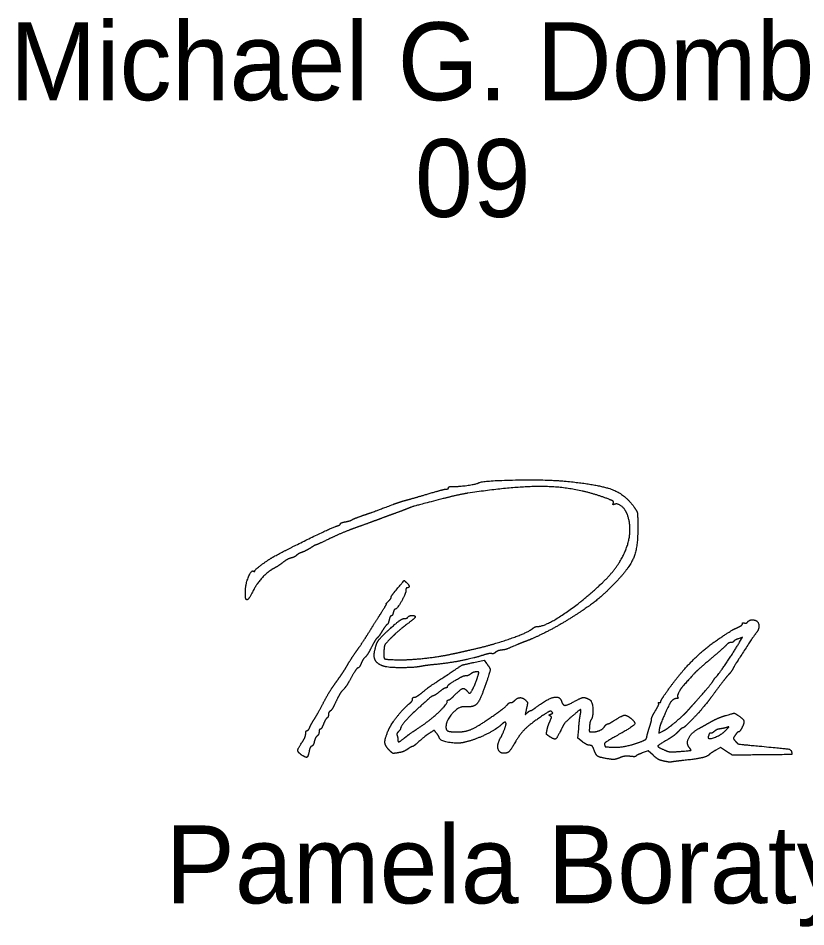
# Model space of a CAD drawing. Extents: x 0 to 40.8, y 0 to 22.
# Drawn here: x 37.682 to 39.097, y 9.315 to 10.949 of the extents above; entities that cross this region are included whole.
import ezdxf

# ---------------------------------------------------------------- set-up
doc = ezdxf.new("R2010")
doc.units = 0
doc.layers.add('Default', color=7, linetype='Continuous')
doc.layers.add('SH_Text', color=7, linetype='Continuous')

msp = doc.modelspace()

# ---------------------------------------------------------------- linework, layer by layer
at = {"layer": 'Default'}
for points in [[(38.9782, 9.8265), (38.9836, 9.8355), (38.9763, 9.8329)], [(38.5009, 9.7904), (38.5189, 9.7944), (38.5236, 9.7882)], [(38.6958, 9.6475), (38.6875, 9.6539), (38.689, 9.6709)], [(38.8338, 9.6695), (38.8328, 9.6631), (38.8415, 9.6675)], [(38.8228, 9.6232), (38.8136, 9.6315), (38.8031, 9.6274)], [(38.9547, 9.6302), (38.944, 9.637), (38.9356, 9.6325)]]:
    msp.add_lwpolyline(points, dxfattribs=at)
for points in [[(38.5083, 10.1129), (38.5151, 10.1171), (38.6321, 10.1194), (38.6665, 10.116)], [(38.6665, 10.116), (38.7258, 10.1102), (38.7733, 10.0919), (38.7891, 10.0689)], [(38.4186, 10.0933), (38.4346, 10.0981), (38.4495, 10.102), (38.4516, 10.102)], [(38.4516, 10.102), (38.4536, 10.102), (38.4553, 10.1031), (38.4553, 10.1045)], [(38.4553, 10.1045), (38.4553, 10.1059), (38.4594, 10.1069), (38.4643, 10.1067)], [(38.4643, 10.1067), (38.4739, 10.1064), (38.5049, 10.1108), (38.5083, 10.1129)], [(38.739, 10.0853), (38.6884, 10.1043), (38.5805, 10.1083), (38.4901, 10.0945)], [(38.3557, 10.0744), (38.3636, 10.0773), (38.3744, 10.0808), (38.3797, 10.0822)], [(38.3797, 10.0822), (38.385, 10.0836), (38.4025, 10.0886), (38.4186, 10.0933)], [(38.4457, 10.0848), (38.3947, 10.0716), (38.3904, 10.0704), (38.3797, 10.066)], [(38.4901, 10.0945), (38.4809, 10.0931), (38.4609, 10.0887), (38.4457, 10.0848)], [(38.7513, 10.0766), (38.7523, 10.0792), (38.7488, 10.0816), (38.739, 10.0853)], [(38.2993, 10.0538), (38.314, 10.0589), (38.3205, 10.0612), (38.3557, 10.0744)], [(38.3797, 10.066), (38.3771, 10.0649), (38.3668, 10.0611), (38.3569, 10.0575)], [(38.7537, 10.0746), (38.7511, 10.0736), (38.7504, 10.0742), (38.7513, 10.0766)], [(38.7771, 10.0547), (38.7739, 10.0644), (38.7594, 10.0768), (38.7537, 10.0746)], [(38.7891, 10.0689), (38.794, 10.0616), (38.795, 10.0573), (38.7953, 10.0394)], [(38.2813, 10.0466), (38.2826, 10.0476), (38.2907, 10.0508), (38.2993, 10.0538)], [(38.3569, 10.0575), (38.347, 10.0539), (38.3319, 10.0483), (38.3233, 10.0451)], [(38.7316, 9.9335), (38.7625, 9.9629), (38.7864, 10.0264), (38.7771, 10.0547)], [(38.1433, 9.9816), (38.1735, 9.9978), (38.2471, 10.0335), (38.2555, 10.0359)], [(38.2873, 10.032), (38.2761, 10.028), (38.2557, 10.0194), (38.2421, 10.013)], [(38.2555, 10.0359), (38.2585, 10.0368), (38.2609, 10.0384), (38.2609, 10.0395)], [(38.2609, 10.0395), (38.2609, 10.0406), (38.265, 10.0422), (38.2699, 10.0431)], [(38.2699, 10.0431), (38.2749, 10.0441), (38.28, 10.0456), (38.2813, 10.0466)], [(38.3233, 10.0451), (38.3147, 10.0419), (38.2985, 10.036), (38.2873, 10.032)], [(38.7953, 10.0394), (38.796, 9.9986), (38.7799, 9.9589), (38.7505, 9.929)], [(38.2162, 10.0012), (38.2157, 10.0012), (38.2112, 9.9987), (38.2063, 9.9955)], [(38.2421, 10.013), (38.2284, 10.0065), (38.2168, 10.0012), (38.2162, 10.0012)], [(38.1822, 9.9829), (38.1804, 9.9811), (38.1761, 9.9789), (38.1725, 9.978)], [(38.1914, 9.988), (38.1882, 9.987), (38.1841, 9.9847), (38.1822, 9.9829)], [(38.2063, 9.9955), (38.2013, 9.9924), (38.1947, 9.9891), (38.1914, 9.988)], [(38.1073, 9.955), (38.1073, 9.9571), (38.1327, 9.9759), (38.1433, 9.9816)], [(38.1577, 9.97), (38.1531, 9.9664), (38.1459, 9.9617), (38.1418, 9.9596)], [(38.1725, 9.978), (38.169, 9.9772), (38.1623, 9.9736), (38.1577, 9.97)], [(38.0901, 9.9171), (38.0902, 9.9303), (38.1009, 9.9569), (38.105, 9.9543)], [(38.105, 9.9543), (38.1063, 9.9536), (38.1073, 9.9538), (38.1073, 9.955)], [(38.1418, 9.9596), (38.1314, 9.9543), (38.1115, 9.9334), (38.1053, 9.9213)], [(38.3575, 9.916), (38.376, 9.9382), (38.3753, 9.9376), (38.3794, 9.9342)], [(38.3794, 9.9342), (38.3837, 9.9307), (38.3847, 9.9244), (38.3809, 9.9244)], [(38.1053, 9.9213), (38.0987, 9.9084), (38.0934, 9.9015), (38.0915, 9.9034)], [(38.3785, 9.9193), (38.3785, 9.9138), (38.3626, 9.886), (38.3594, 9.886)], [(38.3809, 9.9244), (38.3796, 9.9244), (38.3785, 9.9221), (38.3785, 9.9193)], [(38.6149, 9.8548), (38.629, 9.8548), (38.6971, 9.9007), (38.7316, 9.9335)], [(38.7505, 9.929), (38.7319, 9.9101), (38.6995, 9.8852), (38.669, 9.8664)], [(38.0915, 9.9034), (38.0907, 9.9042), (38.0901, 9.9104), (38.0901, 9.9171)], [(38.3473, 9.9004), (38.3499, 9.903), (38.3521, 9.9062), (38.3521, 9.9074)], [(38.3521, 9.9074), (38.3521, 9.9086), (38.3545, 9.9125), (38.3575, 9.916)], [(38.3346, 9.8799), (38.3401, 9.8885), (38.3441, 9.8956), (38.3436, 9.8956)], [(38.3436, 9.8956), (38.343, 9.8956), (38.3447, 9.8978), (38.3473, 9.9004)], [(38.3594, 9.886), (38.3583, 9.886), (38.3567, 9.8833), (38.3559, 9.88)], [(38.3125, 9.8449), (38.3191, 9.8556), (38.329, 9.8713), (38.3346, 9.8799)], [(38.3437, 9.845), (38.3594, 9.8597), (38.3722, 9.8692), (38.3761, 9.8692)], [(38.3522, 9.874), (38.3511, 9.874), (38.3494, 9.8708), (38.3485, 9.8668)], [(38.3559, 9.88), (38.3551, 9.8767), (38.3534, 9.874), (38.3522, 9.874)], [(38.3761, 9.8692), (38.3786, 9.8692), (38.3813, 9.8703), (38.3821, 9.8716)], [(38.3953, 9.872), (38.3953, 9.8709), (38.3886, 9.8649), (38.3803, 9.8588)], [(38.3821, 9.8716), (38.3839, 9.8745), (38.3953, 9.8748), (38.3953, 9.872)], [(38.3446, 9.8582), (38.3434, 9.8574), (38.3395, 9.8523), (38.3361, 9.8468)], [(38.3485, 9.8668), (38.3476, 9.8629), (38.3459, 9.859), (38.3446, 9.8582)], [(38.3803, 9.8588), (38.3721, 9.8527), (38.3595, 9.8419), (38.3525, 9.8347)], [(38.669, 9.8664), (38.6499, 9.8546), (38.6086, 9.8336), (38.5945, 9.8285)], [(38.6067, 9.8515), (38.6088, 9.8533), (38.6125, 9.8548), (38.6149, 9.8548)], [(38.9465, 9.8364), (38.9655, 9.8487), (38.9673, 9.8498), (38.9755, 9.8534)], [(38.9755, 9.8534), (38.9798, 9.8554), (38.9833, 9.8582), (38.9833, 9.8597)], [(38.9833, 9.8597), (38.9833, 9.8613), (38.9848, 9.8619), (38.9867, 9.8612)], [(38.9867, 9.8612), (38.9886, 9.8605), (38.9914, 9.8614), (38.993, 9.8633)], [(38.993, 9.8633), (38.9946, 9.8652), (38.9983, 9.8668), (39.0012, 9.8668)], [(39.0012, 9.8668), (39.0107, 9.8668), (39.0144, 9.8507), (39.007, 9.8418)], [(38.2908, 9.812), (38.2961, 9.8195), (38.3059, 9.8343), (38.3125, 9.8449)], [(38.3224, 9.8104), (38.3251, 9.8234), (38.3313, 9.8334), (38.3437, 9.845)], [(38.3361, 9.8468), (38.3328, 9.8413), (38.3286, 9.8357), (38.327, 9.8344)], [(38.4949, 9.8129), (38.5318, 9.8211), (38.5981, 9.8439), (38.6067, 9.8515)], [(38.8519, 9.7439), (38.8742, 9.7747), (38.9192, 9.8187), (38.9465, 9.8364)], [(39.007, 9.8418), (39.0028, 9.8368), (38.97, 9.7863), (38.9668, 9.7801)], [(38.327, 9.8344), (38.3253, 9.833), (38.3207, 9.8254), (38.3166, 9.8174)], [(38.3525, 9.8347), (38.3418, 9.8238), (38.3396, 9.8201), (38.3391, 9.8119)], [(38.5789, 9.8223), (38.5618, 9.8148), (38.5569, 9.8131), (38.5503, 9.8124)], [(38.5945, 9.8285), (38.5899, 9.8268), (38.5828, 9.824), (38.5789, 9.8223)], [(38.9534, 9.8206), (38.9507, 9.8176), (38.9382, 9.8066), (38.9257, 9.796)], [(38.9354, 9.7636), (38.9382, 9.7655), (38.9665, 9.807), (38.9782, 9.8265)], [(38.9622, 9.826), (38.96, 9.826), (38.9561, 9.8236), (38.9534, 9.8206)], [(38.9676, 9.8282), (38.9668, 9.827), (38.9644, 9.826), (38.9622, 9.826)], [(38.9763, 9.8329), (38.9722, 9.8315), (38.9683, 9.8294), (38.9676, 9.8282)], [(38.274, 9.7864), (38.2779, 9.793), (38.2854, 9.8045), (38.2908, 9.812)], [(38.3166, 9.8174), (38.3126, 9.8094), (38.3075, 9.8014), (38.3054, 9.7996)], [(38.3377, 9.7836), (38.3273, 9.7875), (38.3202, 9.7999), (38.3224, 9.8104)], [(38.3391, 9.8119), (38.3382, 9.7984), (38.3423, 9.7955), (38.3629, 9.795)], [(38.3629, 9.795), (38.3822, 9.7945), (38.44, 9.8006), (38.4613, 9.8054)], [(38.4613, 9.8054), (38.4692, 9.8071), (38.4843, 9.8105), (38.4949, 9.8129)], [(38.5327, 9.8061), (38.531, 9.8067), (38.5229, 9.805), (38.5147, 9.8024)], [(38.5395, 9.8083), (38.5374, 9.8065), (38.5343, 9.8055), (38.5327, 9.8061)], [(38.5503, 9.8124), (38.5464, 9.8119), (38.5416, 9.8101), (38.5395, 9.8083)], [(38.2981, 9.7884), (38.2963, 9.784), (38.2937, 9.7804), (38.2924, 9.7804)], [(38.3054, 9.7996), (38.3032, 9.7978), (38.2999, 9.7928), (38.2981, 9.7884)], [(38.5147, 9.8024), (38.4982, 9.7971), (38.4531, 9.7886), (38.4293, 9.7863)], [(38.4469, 9.7639), (38.4786, 9.785), (38.48, 9.7857), (38.5009, 9.7904)], [(38.5236, 9.7882), (38.5302, 9.7795), (38.53, 9.7746), (38.5223, 9.752)], [(38.9257, 9.796), (38.9061, 9.7795), (38.8944, 9.7681), (38.8777, 9.7492)], [(38.261, 9.7658), (38.2643, 9.7705), (38.2702, 9.7798), (38.274, 9.7864)], [(38.2924, 9.7804), (38.2911, 9.7804), (38.2857, 9.7725), (38.2803, 9.7628)], [(38.4089, 9.7837), (38.3952, 9.7807), (38.3457, 9.7806), (38.3377, 9.7836)], [(38.4293, 9.7863), (38.421, 9.7855), (38.4118, 9.7843), (38.4089, 9.7837)], [(38.5049, 9.7731), (38.5021, 9.7731), (38.4976, 9.7715), (38.495, 9.7695)], [(38.5082, 9.7666), (38.5099, 9.7724), (38.5095, 9.7732), (38.5049, 9.7731)], [(38.9668, 9.7801), (38.9651, 9.7767), (38.9612, 9.7712), (38.9582, 9.768)], [(38.2474, 9.7466), (38.2515, 9.7524), (38.2576, 9.761), (38.261, 9.7658)], [(38.2803, 9.7628), (38.275, 9.7532), (38.2683, 9.7432), (38.2655, 9.7406)], [(38.4077, 9.736), (38.4214, 9.7471), (38.4194, 9.7457), (38.4469, 9.7639)], [(38.4766, 9.7629), (38.4622, 9.7549), (38.4529, 9.7485), (38.4529, 9.7466)], [(38.4863, 9.766), (38.4841, 9.766), (38.4797, 9.7646), (38.4766, 9.7629)], [(38.495, 9.7695), (38.4925, 9.7676), (38.4886, 9.766), (38.4863, 9.766)], [(38.4935, 9.7348), (38.4953, 9.7348), (38.5051, 9.7559), (38.5082, 9.7666)], [(38.9002, 9.7206), (38.9155, 9.7378), (38.9291, 9.7541), (38.9315, 9.7585)], [(38.9315, 9.7585), (38.9327, 9.7606), (38.9345, 9.7629), (38.9354, 9.7636)], [(38.9582, 9.768), (38.9552, 9.7648), (38.9463, 9.7534), (38.9384, 9.7428)], [(38.2286, 9.7144), (38.2348, 9.7263), (38.2433, 9.7407), (38.2474, 9.7466)], [(38.2655, 9.7406), (38.2627, 9.7381), (38.2571, 9.729), (38.2532, 9.7204)], [(38.4502, 9.7444), (38.4488, 9.7444), (38.4435, 9.7412), (38.4385, 9.7372)], [(38.4529, 9.7466), (38.4529, 9.7454), (38.4517, 9.7444), (38.4502, 9.7444)], [(38.4673, 9.7324), (38.4774, 9.7425), (38.484, 9.7443), (38.4889, 9.7384)], [(38.5223, 9.752), (38.5121, 9.7221), (38.5001, 9.7091), (38.4841, 9.7104)], [(38.4889, 9.7384), (38.4905, 9.7364), (38.4926, 9.7348), (38.4935, 9.7348)], [(38.8369, 9.7206), (38.8369, 9.722), (38.8437, 9.7325), (38.8519, 9.7439)], [(38.8777, 9.7492), (38.8719, 9.7426), (38.8656, 9.7297), (38.867, 9.7274)], [(38.9384, 9.7428), (38.9305, 9.7321), (38.9229, 9.7219), (38.9214, 9.7201)], [(38.3851, 9.7164), (38.3881, 9.7188), (38.3905, 9.7223), (38.3905, 9.7242)], [(38.3905, 9.7242), (38.3905, 9.7261), (38.392, 9.7276), (38.3939, 9.7276)], [(38.4274, 9.73), (38.4255, 9.73), (38.417, 9.7227), (38.3917, 9.6995)], [(38.3939, 9.7276), (38.3957, 9.7276), (38.4019, 9.7314), (38.4077, 9.736)], [(38.4385, 9.7372), (38.4335, 9.7332), (38.4285, 9.73), (38.4274, 9.73)], [(38.4529, 9.7197), (38.4529, 9.7214), (38.454, 9.7228), (38.4553, 9.7228)], [(38.4553, 9.7228), (38.4566, 9.7228), (38.462, 9.7271), (38.4673, 9.7324)], [(38.5669, 9.718), (38.5687, 9.718), (38.5719, 9.7198), (38.5741, 9.7219)], [(38.5741, 9.7219), (38.579, 9.7269), (38.589, 9.7269), (38.5939, 9.722)], [(38.5939, 9.722), (38.5971, 9.7188), (38.5973, 9.7163), (38.5952, 9.7072)], [(38.6121, 9.7093), (38.6323, 9.7245), (38.655, 9.7301), (38.658, 9.7207)], [(38.6818, 9.7203), (38.6938, 9.7269), (38.701, 9.7276), (38.7092, 9.723)], [(38.7092, 9.723), (38.7136, 9.7206), (38.7153, 9.6926), (38.7114, 9.6874)], [(38.8648, 9.7252), (38.8584, 9.7252), (38.8489, 9.71), (38.8368, 9.6808)], [(38.867, 9.7274), (38.8678, 9.7262), (38.8668, 9.7252), (38.8648, 9.7252)], [(38.2131, 9.6868), (38.2153, 9.6901), (38.2223, 9.7025), (38.2286, 9.7144)], [(38.2532, 9.7204), (38.2493, 9.7118), (38.2445, 9.7039), (38.2427, 9.7029)], [(38.347, 9.6681), (38.3515, 9.6786), (38.3747, 9.708), (38.3851, 9.7164)], [(38.4068, 9.6762), (38.4224, 9.6866), (38.4529, 9.7154), (38.4529, 9.7197)], [(38.4841, 9.7104), (38.4737, 9.7113), (38.4505, 9.6859), (38.4505, 9.6737)], [(38.5189, 9.6831), (38.5375, 9.6955), (38.5599, 9.7122), (38.5616, 9.7149)], [(38.5616, 9.7149), (38.5627, 9.7166), (38.565, 9.718), (38.5669, 9.718)], [(38.5952, 9.7072), (38.5929, 9.6969), (38.593, 9.6965), (38.5968, 9.6999)], [(38.6027, 9.7036), (38.6036, 9.7036), (38.6079, 9.7062), (38.6121, 9.7093)], [(38.658, 9.7207), (38.6604, 9.7131), (38.6685, 9.713), (38.6818, 9.7203)], [(38.6919, 9.6958), (38.6938, 9.7052), (38.6912, 9.7057), (38.6819, 9.6975)], [(38.8271, 9.7037), (38.831, 9.71), (38.8335, 9.7158), (38.8327, 9.7166)], [(38.8327, 9.7166), (38.8319, 9.7174), (38.8326, 9.718), (38.8341, 9.718)], [(38.8341, 9.718), (38.8356, 9.718), (38.8369, 9.7192), (38.8369, 9.7206)], [(38.8846, 9.7032), (38.8877, 9.7067), (38.8948, 9.7146), (38.9002, 9.7206)], [(38.9214, 9.7201), (38.9081, 9.7037), (38.9036, 9.6985), (38.8917, 9.6863)], [(38.2368, 9.6903), (38.2354, 9.6895), (38.2326, 9.6846), (38.2305, 9.6794)], [(38.2393, 9.6964), (38.2393, 9.6939), (38.2382, 9.6912), (38.2368, 9.6903)], [(38.2427, 9.7029), (38.2408, 9.7018), (38.2393, 9.6989), (38.2393, 9.6964)], [(38.3917, 9.6995), (38.3826, 9.6911), (38.3689, 9.674), (38.3689, 9.671)], [(38.6205, 9.6921), (38.6008, 9.6786), (38.5836, 9.6616), (38.5753, 9.6472)], [(38.5968, 9.6999), (38.599, 9.7019), (38.6017, 9.7036), (38.6027, 9.7036)], [(38.6407, 9.7015), (38.6389, 9.7033), (38.633, 9.7006), (38.6205, 9.6921)], [(38.6379, 9.6939), (38.6357, 9.6952), (38.636, 9.6962), (38.6391, 9.6973)], [(38.6372, 9.684), (38.6401, 9.6903), (38.6402, 9.6924), (38.6379, 9.6939)], [(38.6391, 9.6973), (38.6421, 9.6985), (38.6426, 9.6997), (38.6407, 9.7015)], [(38.6819, 9.6975), (38.6659, 9.6834), (38.6622, 9.679), (38.6567, 9.6677)], [(38.689, 9.6709), (38.6898, 9.6803), (38.6911, 9.6915), (38.6919, 9.6958)], [(38.7827, 9.6898), (38.7924, 9.6822), (38.7856, 9.6742), (38.754, 9.6565)], [(38.7545, 9.6868), (38.7675, 9.695), (38.775, 9.6958), (38.7827, 9.6898)], [(38.8166, 9.6748), (38.8185, 9.6807), (38.8201, 9.6871), (38.8201, 9.6889)], [(38.8201, 9.6889), (38.8201, 9.6908), (38.8233, 9.6974), (38.8271, 9.7037)], [(38.8645, 9.6843), (38.8724, 9.6912), (38.8815, 9.6996), (38.8846, 9.7032)], [(38.9245, 9.6823), (38.9324, 9.6869), (38.9456, 9.6926), (38.9538, 9.695)], [(38.9538, 9.695), (38.9679, 9.6992), (38.969, 9.6993), (38.9749, 9.6954)], [(38.9749, 9.6954), (38.9845, 9.6891), (38.9869, 9.6817), (38.9823, 9.6727)], [(38.201, 9.6676), (38.2023, 9.6676), (38.2047, 9.6706), (38.2062, 9.6742)], [(38.2062, 9.6742), (38.2078, 9.6778), (38.2109, 9.6835), (38.2131, 9.6868)], [(38.2305, 9.6794), (38.2285, 9.6742), (38.2258, 9.67), (38.2246, 9.67)], [(38.3753, 9.6539), (38.3828, 9.66), (38.3881, 9.6637), (38.4068, 9.6762)], [(38.4505, 9.6737), (38.4505, 9.6685), (38.4583, 9.6652), (38.4705, 9.6652)], [(38.4705, 9.6652), (38.4835, 9.6652), (38.5026, 9.6723), (38.5189, 9.6831)], [(38.5509, 9.679), (38.5413, 9.6698), (38.5026, 9.651), (38.4841, 9.6466)], [(38.5479, 9.6532), (38.5521, 9.6609), (38.5585, 9.6771), (38.5585, 9.6799)], [(38.5585, 9.6799), (38.5585, 9.683), (38.5545, 9.6825), (38.5509, 9.679)], [(38.6321, 9.6684), (38.6329, 9.6726), (38.6352, 9.6796), (38.6372, 9.684)], [(38.7085, 9.6748), (38.7079, 9.6672), (38.7086, 9.6652), (38.7118, 9.6652)], [(38.7114, 9.6874), (38.7101, 9.6857), (38.7088, 9.6801), (38.7085, 9.6748)], [(38.7118, 9.6652), (38.7201, 9.6652), (38.7321, 9.67), (38.7354, 9.6747)], [(38.7354, 9.6747), (38.7372, 9.6774), (38.7398, 9.6796), (38.741, 9.6796)], [(38.741, 9.6796), (38.7422, 9.6796), (38.7482, 9.6828), (38.7545, 9.6868)], [(38.8118, 9.6577), (38.8125, 9.6612), (38.8147, 9.6689), (38.8166, 9.6748)], [(38.8368, 9.6808), (38.8358, 9.6782), (38.8344, 9.6731), (38.8338, 9.6695)], [(38.8415, 9.6675), (38.8462, 9.6699), (38.8566, 9.6775), (38.8645, 9.6843)], [(38.8761, 9.6724), (38.875, 9.6724), (38.8711, 9.6693), (38.8675, 9.6654)], [(38.8917, 9.6863), (38.8842, 9.6787), (38.8772, 9.6724), (38.8761, 9.6724)], [(38.9049, 9.6713), (38.9078, 9.6729), (38.9166, 9.6778), (38.9245, 9.6823)], [(38.9557, 9.6736), (38.9531, 9.6727), (38.9477, 9.6714), (38.9439, 9.6709)], [(38.9533, 9.6681), (38.9588, 9.6737), (38.9594, 9.675), (38.9557, 9.6736)], [(38.9823, 9.6727), (38.9801, 9.6686), (38.9775, 9.6652), (38.9763, 9.6652)], [(38.1927, 9.6477), (38.1959, 9.6524), (38.1985, 9.6588), (38.1985, 9.6619)], [(38.1985, 9.6619), (38.1985, 9.665), (38.1996, 9.6676), (38.201, 9.6676)], [(38.2191, 9.6581), (38.2172, 9.6566), (38.2149, 9.652), (38.214, 9.6481)], [(38.2225, 9.6655), (38.2225, 9.663), (38.221, 9.6597), (38.2191, 9.6581)], [(38.2246, 9.67), (38.2235, 9.67), (38.2225, 9.668), (38.2225, 9.6655)], [(38.3487, 9.6324), (38.3411, 9.64), (38.3405, 9.6529), (38.347, 9.6681)], [(38.3652, 9.6659), (38.3631, 9.6639), (38.362, 9.6606), (38.3628, 9.6587)], [(38.3628, 9.6587), (38.3635, 9.6568), (38.3641, 9.6537), (38.3641, 9.6518)], [(38.3689, 9.671), (38.3689, 9.6703), (38.3672, 9.668), (38.3652, 9.6659)], [(38.4226, 9.664), (38.4144, 9.6586), (38.4118, 9.6566), (38.4006, 9.6466)], [(38.4339, 9.6626), (38.4294, 9.6684), (38.4294, 9.6685), (38.4226, 9.664)], [(38.4385, 9.6553), (38.4384, 9.6561), (38.4364, 9.6594), (38.4339, 9.6626)], [(38.6367, 9.6569), (38.6317, 9.6601), (38.6309, 9.6621), (38.6321, 9.6684)], [(38.6567, 9.6677), (38.65, 9.654), (38.6452, 9.6513), (38.6367, 9.6569)], [(38.754, 9.6565), (38.7407, 9.6491), (38.7345, 9.6443), (38.7354, 9.6421)], [(38.7991, 9.6471), (38.8079, 9.6505), (38.8109, 9.6529), (38.8118, 9.6577)], [(38.8675, 9.6654), (38.8639, 9.6616), (38.8558, 9.6555), (38.8495, 9.6518)], [(38.8879, 9.6369), (38.8818, 9.6444), (38.8916, 9.6641), (38.9049, 9.6713)], [(38.9219, 9.6571), (38.9194, 9.6505), (38.9448, 9.6595), (38.9533, 9.6681)], [(38.9233, 9.6618), (38.9233, 9.6612), (38.9227, 9.6591), (38.9219, 9.6571)], [(38.9261, 9.6628), (38.9246, 9.6628), (38.9233, 9.6623), (38.9233, 9.6618)], [(38.9329, 9.6664), (38.9307, 9.6644), (38.9277, 9.6628), (38.9261, 9.6628)], [(38.9439, 9.6709), (38.94, 9.6704), (38.9351, 9.6684), (38.9329, 9.6664)], [(38.9704, 9.6594), (38.9669, 9.654), (38.967, 9.6532), (38.9708, 9.6484)], [(38.9763, 9.6652), (38.9752, 9.6652), (38.9725, 9.6626), (38.9704, 9.6594)], [(38.191, 9.624), (38.184, 9.6289), (38.1845, 9.6356), (38.1927, 9.6477)], [(38.2093, 9.6397), (38.2076, 9.639), (38.2055, 9.6349), (38.2047, 9.6305)], [(38.214, 9.6481), (38.2132, 9.6441), (38.211, 9.6403), (38.2093, 9.6397)], [(38.3641, 9.6518), (38.3641, 9.6469), (38.3675, 9.6476), (38.3753, 9.6539)], [(38.4006, 9.6466), (38.3958, 9.6423), (38.391, 9.6388), (38.3899, 9.6388)], [(38.4841, 9.6466), (38.4712, 9.6435), (38.4386, 9.6497), (38.4385, 9.6553)], [(38.5546, 9.6268), (38.5463, 9.6268), (38.5422, 9.6426), (38.5479, 9.6532)], [(38.5753, 9.6472), (38.5671, 9.6331), (38.5608, 9.6268), (38.5546, 9.6268)], [(38.7088, 9.6412), (38.7063, 9.6412), (38.7004, 9.6441), (38.6958, 9.6475)], [(38.7164, 9.6334), (38.7145, 9.6386), (38.712, 9.6412), (38.7088, 9.6412)], [(38.7354, 9.6421), (38.7367, 9.6387), (38.7374, 9.6385), (38.7493, 9.6378)], [(38.7493, 9.6378), (38.7598, 9.6371), (38.786, 9.642), (38.7991, 9.6471)], [(38.8495, 9.6518), (38.8316, 9.6414), (38.8306, 9.6381), (38.8435, 9.6326)], [(38.9708, 9.6484), (38.9744, 9.6439), (38.9794, 9.6429), (39.0133, 9.6398)], [(39.0133, 9.6398), (39.0624, 9.6352), (39.0707, 9.6337), (39.0716, 9.6289)], [(38.2047, 9.6305), (38.2028, 9.6207), (38.1987, 9.6187), (38.191, 9.624)], [(38.3649, 9.6278), (38.3562, 9.6264), (38.354, 9.6271), (38.3487, 9.6324)], [(38.3814, 9.6341), (38.3778, 9.6315), (38.3704, 9.6286), (38.3649, 9.6278)], [(38.3899, 9.6388), (38.3888, 9.6388), (38.385, 9.6367), (38.3814, 9.6341)], [(38.7417, 9.6169), (38.7267, 9.6193), (38.7199, 9.6237), (38.7164, 9.6334)], [(38.8031, 9.6274), (38.7973, 9.6252), (38.7922, 9.6226), (38.7918, 9.6217)], [(38.8374, 9.6138), (38.8344, 9.6144), (38.8279, 9.6186), (38.8228, 9.6232)], [(38.8435, 9.6326), (38.8503, 9.6297), (38.8568, 9.6291), (38.8703, 9.6302)], [(38.8703, 9.6302), (38.8898, 9.6317), (38.8916, 9.6324), (38.8879, 9.6369)], [(38.9239, 9.6247), (38.9202, 9.6209), (38.8987, 9.6161), (38.8753, 9.6137)], [(38.9356, 9.6325), (38.931, 9.63), (38.9258, 9.6265), (38.9239, 9.6247)], [(39.0013, 9.6238), (38.9656, 9.6234), (38.9652, 9.6235), (38.9547, 9.6302)], [(39.0716, 9.6289), (39.0724, 9.6247), (39.0704, 9.6245), (39.0013, 9.6238)], [(38.7628, 9.6188), (38.7559, 9.616), (38.7503, 9.6155), (38.7417, 9.6169)], [(38.7817, 9.6213), (38.7759, 9.6221), (38.7686, 9.6211), (38.7628, 9.6188)], [(38.7918, 9.6217), (38.7914, 9.6208), (38.7868, 9.6207), (38.7817, 9.6213)], [(38.8477, 9.6116), (38.8451, 9.6121), (38.8404, 9.6131), (38.8374, 9.6138)], [(38.8561, 9.6113), (38.8541, 9.6109), (38.8503, 9.6111), (38.8477, 9.6116)], [(38.8753, 9.6137), (38.8667, 9.6128), (38.8581, 9.6117), (38.8561, 9.6113)]]:
    msp.add_open_spline(points, degree=2, dxfattribs=at)

# ---------------------------------------------------------------- texts
at = {"layer": 'SH_Text'}
for s, p in [('Michael G. Dombrowski', (37.6665, 10.8012)), ('              09', (37.6665, 10.5912)), ('Pamela Boratyn', (37.9464, 9.3571))]:
    msp.add_text(s, height=0.14, dxfattribs=at).set_placement(p)

doc.saveas('drawing.dxf')
